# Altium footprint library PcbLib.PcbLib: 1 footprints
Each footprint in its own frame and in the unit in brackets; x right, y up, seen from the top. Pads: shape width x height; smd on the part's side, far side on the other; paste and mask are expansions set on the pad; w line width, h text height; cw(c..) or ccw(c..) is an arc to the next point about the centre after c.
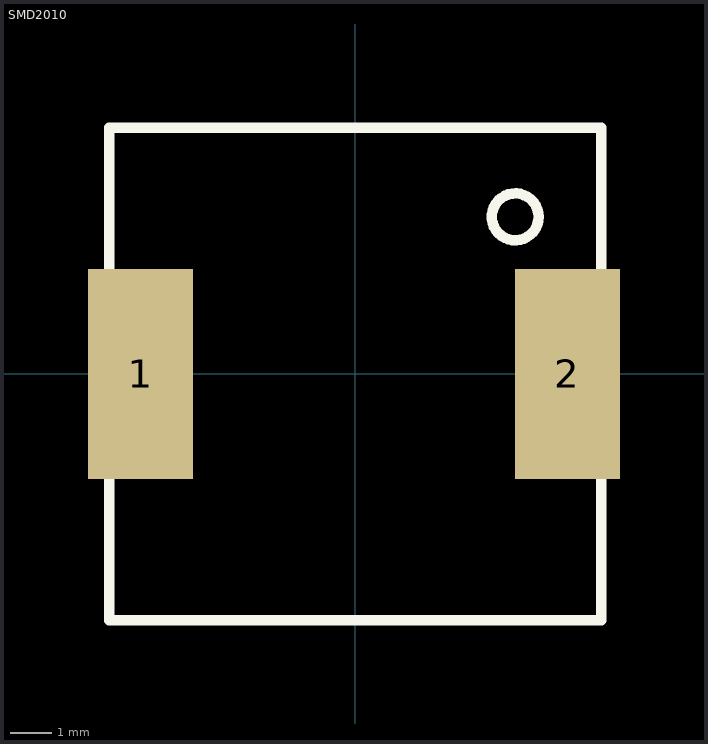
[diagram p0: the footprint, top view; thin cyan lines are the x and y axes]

## SMD2010 [mil] "www.mailshop.cn"
pads (2):
  rect 100x200 smd: 1(-205,0) 2(202.5,0)
Top Overlay:
  circle w10: c152.64,150 r22.36
  lines w10: -235,-235 -235,235 235,235 235,-235 -235,-235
